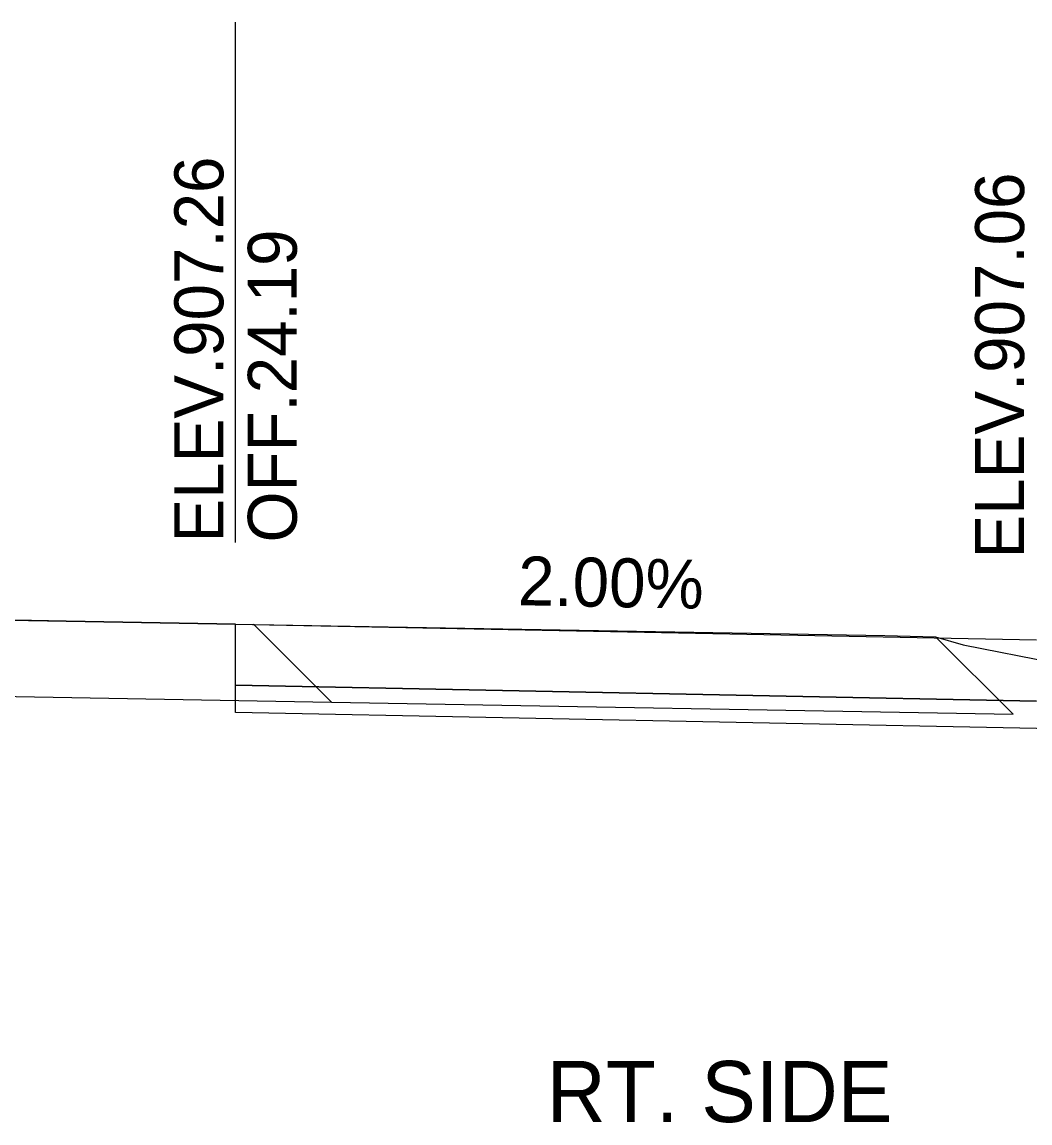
# Model space of a CAD drawing. Extents: x -4 to 359, y 0 to 1436.
# Drawn here: x 274.07 to 286.42, y 1356.1 to 1369.59 of the extents above; entities that cross this region are included whole.
import ezdxf

# ---------------------------------------------------------------- set-up
doc = ezdxf.new("R2010")
doc.units = 0
for name, color, linetype in [('XS-Existing subsurface-pavement', 7, 'Continuous'), ('XS-Existing subsurface-shoulder', 7, 'Continuous'), ('XS-Existing surface-ground', 7, 'Continuous'), ('XS-Proposed Finish Grade', 7, 'Continuous'), ('XS-Proposed subsurface-aggregate layer 1', 7, 'Continuous'), ('XS-Proposed surface-pavement', 7, 'Continuous'), ('XS-Text-earthwork labels', 7, 'Continuous'), ('XS-Text-pavement elevation', 7, 'Continuous'), ('XS-Text-pavement slope', 7, 'Continuous'), ('XS-Text-profile report', 7, 'Continuous'), ('XS-Text-tie offset', 7, 'Continuous')]:
    doc.layers.add(name, color=color, linetype=linetype)

msp = doc.modelspace()

# ---------------------------------------------------------------- linework, layer by layer
at = {"layer": 'XS-Existing subsurface-pavement'}
for p in [(276.909, 1362.213), (253.498, 1361.703)]:
    msp.add_line(p, (277.865, 1361.258), dxfattribs=at)
at = {"layer": 'XS-Existing subsurface-shoulder'}
for p in [(285.265, 1362.06), (277.865, 1361.258)]:
    msp.add_line(p, (286.215, 1361.11), dxfattribs=at)
at = {"layer": 'XS-Existing surface-ground'}
for p, q in [((253.515, 1362.64), (276.69, 1362.217)), ((276.69, 1362.217), (284.645, 1362.076)), ((284.645, 1362.076), (285.265, 1362.06)), ((285.265, 1362.06), (285.602, 1361.96)), ((285.602, 1361.96), (295.686, 1360))]:
    msp.add_line(p, q, dxfattribs=at)
at = {"layer": 'XS-Proposed Finish Grade'}
for points in [[(236.854, 1362.36), (252.5, 1362.644), (276.69, 1362.217)], [(276.69, 1362.217), (286.5, 1362.021)]]:
    msp.add_lwpolyline(points, dxfattribs=at)
at = {"layer": 'XS-Proposed subsurface-aggregate layer 1'}
for points in [[(276.69, 1361.467), (286.5, 1361.271)], [(276.69, 1361.133), (276.69, 1361.467)], [(291.039, 1360.846), (286.5, 1360.937), (276.69, 1361.133)]]:
    msp.add_lwpolyline(points, dxfattribs=at)
at = {"layer": 'XS-Proposed surface-pavement'}
for points in [[(236.854, 1362.36), (252.5, 1362.644), (276.69, 1362.217)], [(276.69, 1362.217), (252.5, 1362.644), (236.854, 1362.36)], [(276.69, 1362.217), (286.5, 1362.021)], [(276.69, 1361.467), (276.69, 1362.217)], [(276.69, 1362.217), (276.69, 1362.217)], [(286.5, 1361.271), (276.69, 1361.467)]]:
    msp.add_lwpolyline(points, dxfattribs=at)
at = {"layer": 'XS-Text-tie offset'}
msp.add_line((276.69, 1363.217), (276.69, 1369.595), dxfattribs=at)

# ---------------------------------------------------------------- texts
at = {"layer": 'XS-Text-earthwork labels'}
msp.add_text('RT. SIDE', height=0.75, dxfattribs=at).set_placement((280.501, 1356.112))
at = {"layer": 'XS-Text-pavement elevation'}
for s, p in [('ELEV.907.26', (276.54, 1363.217)), ('ELEV.907.06', (286.35, 1363.021)), ('OFF.24.19', (277.44, 1363.217))]:
    msp.add_text(s, height=0.6, rotation=90, dxfattribs=at).set_placement(p)
at = {"layer": 'XS-Text-pavement slope'}
msp.add_text('2.00%', height=0.6, rotation=358.8542, dxfattribs=at).set_placement((280.145, 1362.448))
at = {"layer": 'XS-Text-profile report'}
for s, p in [('Pvmt_Surf_Asph_T1_R', (276.674, 1362.216)), ('Pvmt_Surf_Asph_T_R', (276.675, 1362.216)), ('Pvmt_Surf_Conc_B_R', (276.675, 1361.466)), ('Agg_Layer_1_B2', (276.678, 1361.133))]:
    msp.add_text(s, height=0.00167, dxfattribs=at).set_placement(p)

doc.saveas('drawing.dxf')
